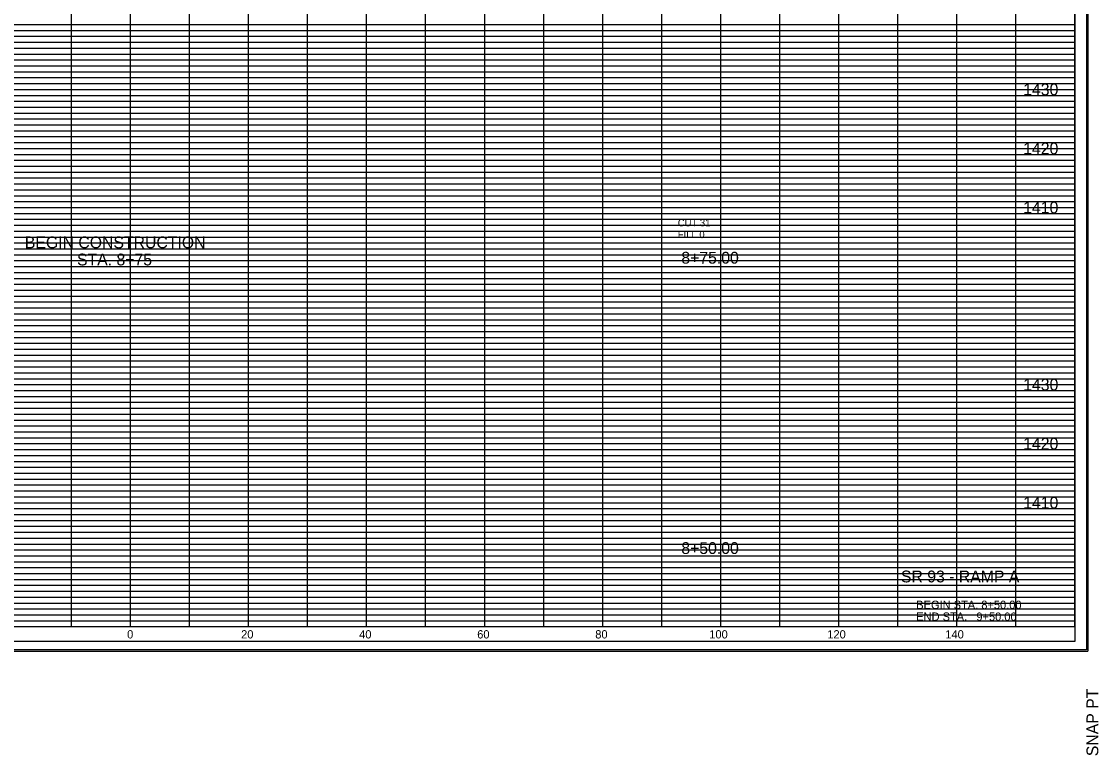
# Model space of a CAD drawing. Extents: x 980 to 1324, y 978 to 1227.
# Drawn here: x 1141.5 to 1324, y 978.2 to 1102.5 of the extents above; entities that cross this region are included whole.
import ezdxf

# ---------------------------------------------------------------- set-up
doc = ezdxf.new("R2010")
doc.units = 0
for name, color, linetype in [('DESIGN - SHEET - Corner Text', 7, 'Continuous'), ('DESIGN - SHEET - Light Grid', 7, 'Continuous'), ('DESIGN - SHEET - Linework', 7, 'Continuous'), ('DESIGN - SHEET - Plot Shape', 7, 'Continuous'), ('DESIGN - TYPICAL - Text', 7, 'Continuous')]:
    doc.layers.add(name, color=color, linetype=linetype)

msp = doc.modelspace()

# ---------------------------------------------------------------- linework, layer by layer
at = {"layer": 'DESIGN - SHEET - Light Grid'}
for p, q in [((1080, 1102), (1160, 1102)), ((1080, 1101), (1160, 1101)), ((1160, 1102), (1240, 1102)), ((1160, 1101), (1240, 1101)), ((1240, 1102), (1320, 1102)), ((1240, 1101), (1320, 1101)), ((1080, 1099), (1160, 1099)), ((1160, 1099), (1240, 1099)), ((1240, 1099), (1320, 1099)), ((1080, 1098), (1160, 1098)), ((1080, 1097), (1160, 1097)), ((1160, 1098), (1240, 1098)), ((1160, 1097), (1240, 1097)), ((1240, 1098), (1320, 1098)), ((1240, 1097), (1320, 1097)), ((1080, 1096), (1160, 1096)), ((1080, 1095), (1160, 1095)), ((1160, 1096), (1240, 1096)), ((1160, 1095), (1240, 1095)), ((1240, 1096), (1320, 1096)), ((1240, 1095), (1320, 1095)), ((1080, 1094), (1160, 1094)), ((1080, 1093), (1160, 1093)), ((1160, 1094), (1240, 1094)), ((1160, 1093), (1240, 1093)), ((1240, 1094), (1320, 1094)), ((1240, 1093), (1320, 1093)), ((1080, 1092), (1160, 1092)), ((1160, 1092), (1240, 1092)), ((1240, 1092), (1320, 1092)), ((1080, 1091), (1160, 1091)), ((1160, 1091), (1240, 1091)), ((1240, 1091), (1320, 1091)), ((1080, 1089), (1160, 1089)), ((1080, 1088), (1160, 1088)), ((1160, 1089), (1240, 1089)), ((1160, 1088), (1240, 1088)), ((1240, 1089), (1320, 1089)), ((1240, 1088), (1320, 1088)), ((1080, 1087), (1160, 1087)), ((1080, 1086), (1160, 1086)), ((1160, 1087), (1240, 1087)), ((1160, 1086), (1240, 1086)), ((1240, 1087), (1320, 1087)), ((1240, 1086), (1320, 1086)), ((1080, 1085), (1160, 1085)), ((1080, 1084), (1160, 1084)), ((1160, 1085), (1240, 1085)), ((1160, 1084), (1240, 1084)), ((1240, 1085), (1320, 1085)), ((1240, 1084), (1320, 1084)), ((1080, 1083), (1160, 1083)), ((1160, 1083), (1240, 1083)), ((1240, 1083), (1320, 1083)), ((1080, 1082), (1160, 1082)), ((1080, 1081), (1160, 1081)), ((1160, 1082), (1240, 1082)), ((1160, 1081), (1240, 1081)), ((1240, 1082), (1320, 1082)), ((1240, 1081), (1320, 1081)), ((1080, 1079), (1160, 1079)), ((1160, 1079), (1240, 1079)), ((1240, 1079), (1320, 1079)), ((1080, 1078), (1160, 1078)), ((1080, 1077), (1160, 1077)), ((1160, 1078), (1240, 1078)), ((1160, 1077), (1240, 1077)), ((1240, 1078), (1320, 1078)), ((1240, 1077), (1320, 1077)), ((1080, 1076), (1160, 1076)), ((1080, 1075), (1160, 1075)), ((1160, 1076), (1240, 1076)), ((1160, 1075), (1240, 1075)), ((1240, 1076), (1320, 1076)), ((1240, 1075), (1320, 1075)), ((1080, 1074), (1160, 1074)), ((1080, 1073), (1160, 1073)), ((1160, 1074), (1240, 1074)), ((1160, 1073), (1240, 1073)), ((1240, 1074), (1320, 1074)), ((1240, 1073), (1320, 1073)), ((1080, 1072), (1160, 1072)), ((1160, 1072), (1240, 1072)), ((1240, 1072), (1320, 1072)), ((1080, 1071), (1160, 1071)), ((1160, 1071), (1240, 1071)), ((1240, 1071), (1320, 1071)), ((1080, 1069), (1160, 1069)), ((1080, 1068), (1160, 1068)), ((1160, 1069), (1240, 1069)), ((1160, 1068), (1240, 1068)), ((1240, 1069), (1320, 1069)), ((1240, 1068), (1320, 1068)), ((1080, 1067), (1160, 1067)), ((1080, 1066), (1160, 1066)), ((1160, 1067), (1240, 1067)), ((1160, 1066), (1240, 1066)), ((1240, 1067), (1320, 1067)), ((1240, 1066), (1320, 1066)), ((1080, 1065), (1160, 1065)), ((1080, 1064), (1160, 1064)), ((1160, 1065), (1240, 1065)), ((1160, 1064), (1240, 1064)), ((1240, 1065), (1320, 1065)), ((1240, 1064), (1320, 1064)), ((1080, 1063), (1160, 1063)), ((1080, 1062), (1160, 1062)), ((1160, 1063), (1240, 1063)), ((1160, 1062), (1240, 1062)), ((1240, 1063), (1320, 1063)), ((1240, 1062), (1320, 1062)), ((1080, 1061), (1160, 1061)), ((1160, 1061), (1240, 1061)), ((1240, 1061), (1320, 1061)), ((1080, 1059), (1160, 1059)), ((1160, 1059), (1240, 1059)), ((1240, 1059), (1320, 1059)), ((1080, 1058), (1160, 1058)), ((1080, 1057), (1160, 1057)), ((1160, 1058), (1240, 1058)), ((1160, 1057), (1240, 1057)), ((1240, 1058), (1320, 1058)), ((1240, 1057), (1320, 1057)), ((1080, 1056), (1160, 1056)), ((1080, 1055), (1160, 1055)), ((1160, 1056), (1240, 1056)), ((1160, 1055), (1240, 1055)), ((1240, 1056), (1320, 1056)), ((1240, 1055), (1320, 1055)), ((1080, 1054), (1160, 1054)), ((1080, 1053), (1160, 1053)), ((1160, 1054), (1240, 1054)), ((1160, 1053), (1240, 1053)), ((1240, 1054), (1320, 1054)), ((1240, 1053), (1320, 1053)), ((1080, 1052), (1160, 1052)), ((1160, 1052), (1240, 1052)), ((1240, 1052), (1320, 1052)), ((1080, 1051), (1160, 1051)), ((1160, 1051), (1240, 1051)), ((1240, 1051), (1320, 1051)), ((1080, 1049), (1160, 1049)), ((1080, 1048), (1160, 1048)), ((1160, 1049), (1240, 1049)), ((1160, 1048), (1240, 1048)), ((1240, 1049), (1320, 1049)), ((1240, 1048), (1320, 1048)), ((1080, 1047), (1160, 1047)), ((1080, 1046), (1160, 1046)), ((1160, 1047), (1240, 1047)), ((1160, 1046), (1240, 1046)), ((1240, 1047), (1320, 1047)), ((1240, 1046), (1320, 1046)), ((1080, 1045), (1160, 1045)), ((1080, 1044), (1160, 1044)), ((1160, 1045), (1240, 1045)), ((1160, 1044), (1240, 1044)), ((1240, 1045), (1320, 1045)), ((1240, 1044), (1320, 1044)), ((1080, 1043), (1160, 1043)), ((1080, 1042), (1160, 1042)), ((1160, 1043), (1240, 1043)), ((1160, 1042), (1240, 1042)), ((1240, 1043), (1320, 1043)), ((1240, 1042), (1320, 1042)), ((1080, 1041), (1160, 1041)), ((1160, 1041), (1240, 1041)), ((1240, 1041), (1320, 1041)), ((1080, 1039), (1160, 1039)), ((1160, 1039), (1240, 1039)), ((1240, 1039), (1320, 1039)), ((1080, 1038), (1160, 1038)), ((1080, 1037), (1160, 1037)), ((1160, 1038), (1240, 1038)), ((1160, 1037), (1240, 1037)), ((1240, 1038), (1320, 1038)), ((1240, 1037), (1320, 1037)), ((1080, 1036), (1160, 1036)), ((1080, 1035), (1160, 1035)), ((1160, 1036), (1240, 1036)), ((1160, 1035), (1240, 1035)), ((1240, 1036), (1320, 1036)), ((1240, 1035), (1320, 1035)), ((1080, 1034), (1160, 1034)), ((1080, 1033), (1160, 1033)), ((1160, 1034), (1240, 1034)), ((1160, 1033), (1240, 1033)), ((1240, 1034), (1320, 1034)), ((1240, 1033), (1320, 1033)), ((1080, 1032), (1160, 1032)), ((1080, 1031), (1160, 1031)), ((1160, 1032), (1240, 1032)), ((1160, 1031), (1240, 1031)), ((1240, 1032), (1320, 1032)), ((1240, 1031), (1320, 1031)), ((1080, 1029), (1160, 1029)), ((1080, 1028), (1160, 1028)), ((1160, 1029), (1240, 1029)), ((1160, 1028), (1240, 1028)), ((1240, 1029), (1320, 1029)), ((1240, 1028), (1320, 1028)), ((1080, 1027), (1160, 1027)), ((1080, 1026), (1160, 1026)), ((1160, 1027), (1240, 1027)), ((1160, 1026), (1240, 1026)), ((1240, 1027), (1320, 1027)), ((1240, 1026), (1320, 1026)), ((1080, 1025), (1160, 1025)), ((1080, 1024), (1160, 1024)), ((1160, 1025), (1240, 1025)), ((1160, 1024), (1240, 1024)), ((1240, 1025), (1320, 1025)), ((1240, 1024), (1320, 1024)), ((1080, 1023), (1160, 1023)), ((1080, 1022), (1160, 1022)), ((1160, 1023), (1240, 1023)), ((1160, 1022), (1240, 1022)), ((1240, 1023), (1320, 1023)), ((1240, 1022), (1320, 1022)), ((1080, 1021), (1160, 1021)), ((1160, 1021), (1240, 1021)), ((1240, 1021), (1320, 1021)), ((1080, 1019), (1160, 1019)), ((1160, 1019), (1240, 1019)), ((1240, 1019), (1320, 1019)), ((1080, 1018), (1160, 1018)), ((1080, 1017), (1160, 1017)), ((1160, 1018), (1240, 1018)), ((1160, 1017), (1240, 1017)), ((1240, 1018), (1320, 1018)), ((1240, 1017), (1320, 1017)), ((1080, 1016), (1160, 1016)), ((1080, 1015), (1160, 1015)), ((1160, 1016), (1240, 1016)), ((1160, 1015), (1240, 1015)), ((1240, 1016), (1320, 1016)), ((1240, 1015), (1320, 1015)), ((1080, 1014), (1160, 1014)), ((1080, 1013), (1160, 1013)), ((1160, 1014), (1240, 1014)), ((1160, 1013), (1240, 1013)), ((1240, 1014), (1320, 1014)), ((1240, 1013), (1320, 1013)), ((1080, 1012), (1160, 1012)), ((1080, 1011), (1160, 1011)), ((1160, 1012), (1240, 1012)), ((1160, 1011), (1240, 1011)), ((1240, 1012), (1320, 1012)), ((1240, 1011), (1320, 1011)), ((1080, 1009), (1160, 1009)), ((1080, 1008), (1160, 1008)), ((1160, 1009), (1240, 1009)), ((1160, 1008), (1240, 1008)), ((1240, 1009), (1320, 1009)), ((1240, 1008), (1320, 1008)), ((1080, 1007), (1160, 1007)), ((1080, 1006), (1160, 1006)), ((1160, 1007), (1240, 1007)), ((1160, 1006), (1240, 1006)), ((1240, 1007), (1320, 1007)), ((1240, 1006), (1320, 1006)), ((1080, 1005), (1160, 1005)), ((1080, 1004), (1160, 1004)), ((1160, 1005), (1240, 1005)), ((1160, 1004), (1240, 1004)), ((1240, 1005), (1320, 1005)), ((1240, 1004), (1320, 1004)), ((1080, 1003), (1160, 1003)), ((1080, 1002), (1160, 1002)), ((1160, 1003), (1240, 1003)), ((1160, 1002), (1240, 1002)), ((1240, 1003), (1320, 1003)), ((1240, 1002), (1320, 1002)), ((1080, 1001), (1160, 1001)), ((1160, 1001), (1240, 1001)), ((1240, 1001), (1320, 1001))]:
    msp.add_line(p, q, dxfattribs=at)
at = {"layer": 'DESIGN - SHEET - Linework'}
for p, q in [((1322.17, 1214.14), (1322.17, 995.86)), ((1150, 1000), (1150, 1210)), ((1160, 1000), (1160, 1210)), ((1170, 1000), (1170, 1210)), ((1180, 1000), (1180, 1210)), ((1190, 1000), (1190, 1210)), ((1200, 1000), (1200, 1210)), ((1210, 1000), (1210, 1210)), ((1220, 1000), (1220, 1210)), ((1230, 1000), (1230, 1210)), ((1240, 1000), (1240, 1210)), ((1250, 1000), (1250, 1210)), ((1260, 1000), (1260, 1210)), ((1270, 1000), (1270, 1210)), ((1280, 1000), (1280, 1200)), ((1290, 1000), (1290, 1200)), ((1300, 1000), (1300, 1200)), ((1310, 1000), (1310, 1200)), ((1000, 1100), (1320, 1100)), ((1000, 1090), (1320, 1090)), ((1000, 1080), (1320, 1080)), ((1000, 1070), (1320, 1070)), ((1000, 1060), (1320, 1060)), ((1000, 1050), (1320, 1050)), ((1000, 1040), (1320, 1040)), ((1000, 1030), (1320, 1030)), ((1000, 1020), (1320, 1020)), ((1000, 1010), (1320, 1010)), ((981.77, 995.86), (1322.17, 995.86))]:
    msp.add_line(p, q, dxfattribs=at)
msp.add_lwpolyline([(1000, 1210), (1000, 1000), (1320, 1000), (1320, 1210), (1000, 1210)], dxfattribs=at)
at = {"layer": 'DESIGN - SHEET - Plot Shape'}
for points in [[(981.97, 1213.94), (1321.97, 1213.94), (1321.97, 996.06), (981.97, 996.06)], [(991.5, 1210), (1320, 1210), (1320, 997.5), (991.5, 997.5)]]:
    msp.add_lwpolyline(points, close=True, dxfattribs=at)

# ---------------------------------------------------------------- texts
at = {"layer": 'DESIGN - SHEET - Corner Text'}
for s, height, p in [('1430', 2, (1311.25, 1090)), ('1420', 2, (1311.25, 1080)), ('1410', 2, (1311.25, 1070)), ('8+75.00', 2, (1253.32, 1061.49)), ('1430', 2, (1311.25, 1040)), ('1420', 2, (1311.25, 1030)), ('1410', 2, (1311.25, 1020)), ('8+50.00', 2, (1253.32, 1012.31)), ('SR 93 - RAMP A', 2, (1290.53, 1007.5)), ('BEGIN STA. 8+50.00', 1.4, (1293.12, 1003)), ('END STA.   9+50.00', 1.4, (1293.12, 1001)), ('0', 1.4, (1159.42, 998)), ('0', 1.4, (1159.42, 998)), ('20', 1.4, (1178.74, 998)), ('40', 1.4, (1198.74, 998)), ('60', 1.4, (1218.74, 998)), ('80', 1.4, (1238.74, 998)), ('100', 1.4, (1258.06, 998)), ('120', 1.4, (1278.06, 998)), ('140', 1.4, (1298.06, 998))]:
    msp.add_text(s, height=height, dxfattribs=at).set_placement(p)
msp.add_text('SNAP PT  ', height=2, rotation=90, dxfattribs=at).set_placement((1323.97, 978.06))
at = {"layer": 'DESIGN - TYPICAL - Text'}
for s, height, p in [('CUT 31', 1.2, (1252.72, 1067.81)), ('BEGIN CONSTRUCTION', 2, (1142.09, 1064.09)), ('FILL 0', 1.2, (1252.72, 1065.81)), ('STA. 8+75', 2, (1150.93, 1061.19))]:
    msp.add_text(s, height=height, dxfattribs=at).set_placement(p)

doc.saveas('drawing.dxf')
